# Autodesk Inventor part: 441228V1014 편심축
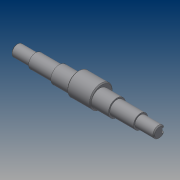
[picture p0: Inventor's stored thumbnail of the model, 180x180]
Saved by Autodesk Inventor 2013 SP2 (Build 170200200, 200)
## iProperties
Created: 2014-12
Part Number: 441228V1014 편심축
Material: Generic
Document SubType Name: Modeling
Designer: CADB105
Density: 1 g/cm^3
Author: CADB105
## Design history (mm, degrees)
sketch "스케치1"
  geometry: L1 (-75.5, 0)-(75.5, 0); L2 (-75.5, 0)-(-75.5, 6); L3 (-75.5, 6)-(-55.5, 6); L4 (-55.5, 6)-(-55.5, 7.5); L5 (-55.5, 7.5)-(-30.5, 7.5); L6 (-30.5, 7.5)-(-30.5, 9); L7 (-30.5, 9)-(30.5, 9); L8 (30.5, 9)-(30.5, 7.5); L9 (30.5, 7.5)-(55.5, 7.5); L10 (55.5, 7.5)-(55.5, 6); L11 (55.5, 6)-(75.5, 6); L12 (75.5, 6)-(75.5, 0); L13 (-12.5, 14)-(12.5, 14); L14 (12.5, 14)-(12.5, 2); L15 (12.5, 2)-(-12.5, 2); L16 (-12.5, 2)-(-12.5, 14); 2 further points
  constraints: 32 end point, 9 parallel, 5 perpendicular, 2 horizontal, 1 coincident, 1 midpoint
  dimensions: "d0" = 151 distance of L1.start L1.end; "d2" = 12 diameter of L3 L1; "d3" = 15 diameter of L5 L1; "d4" = 18 diameter of L7 L1; "d5" = 12 diameter of L11 L1; "d6" = 15 diameter of L9 L1; "d7" = 20 distance of L10.end L11.end; "d8" = 25 distance of L8.end L9.end; "d9" = 20 distance of L2.end L3.end; "d10" = 25 distance of L4.end L5.end; "d12" = 2 distance from line of L15 point (0, 0); "d13" = 24 diameter of L13 L15; "d14" = 18 distance from line of L16 L5.end; "d15" = 18 distance from line of L14 L8.end
revolve "회전1" stored, may be unused: angle "d16" = 90 deg
revolve "회전2" stored, may be unused: angle "d17" = 90 deg
node "작업 평면1"
sketch "스케치2"
  geometry: L1 (75.5, -2.5)-(64, -2.5); L2 (61.5, 0)-(61.5, 0); L3 (64, 2.5)-(75.5, 2.5); L4 (75.5, 2.5)-(75.5, -2.5); L5 (75.5, 6)-(75.5, -6) reference; A1 r 2.5 centre (64, 0) between (61.5, 0) and (64, -2.5); A2 r 2.5 centre (64, 0) between (64, 2.5) and (61.5, 0); 1 further point
  constraints: 8 end point, 4 point on circle, 4 tangent, 2 centre point, 2 parallel, 1 collinear, 1 concentric, 1 horizontal, 1 horizontal alignment, 1 perpendicular
  dimensions: "d19" = 5 distance between parallel lines of L1 L3; "d21" = 2.5 radius of A1; "d22" = 14 distance from line of L2.start L4
extrude "돌출1" cut sketch "스케치2" distance "d23" = 3; taper "d24" = 0 deg
sketch "스케치3"
  geometry: 1 further point
sketch "스케치4"
  geometry: L1 (-75.5, 2.5)-(-64, 2.5); L2 (-61.5, 0)-(-61.5, 0); L3 (-64, -2.5)-(-75.5, -2.5); L4 (-75.5, -2.5)-(-75.5, 2.5); L5 (-75.5, 6)-(-75.5, -6) reference; A1 r 2.5 centre (-64, 0) between (-61.5, 0) and (-64, 2.5); A2 r 2.5 centre (-64, 0) between (-64, -2.5) and (-61.5, 0); 1 further point
  constraints: 8 end point, 4 point on circle, 4 tangent, 2 centre point, 2 parallel, 1 collinear, 1 concentric, 1 horizontal, 1 horizontal alignment, 1 perpendicular
  dimensions: "d25" = 5 distance between parallel lines of L1 L3; "d27" = 2.5 radius of A1; "d28" = 14 distance from line of L2.start L4
extrude "돌출2" cut sketch "스케치4" distance "d29" = 3; taper "d30" = 0 deg
chamfer "모따기1" distance "d31" = 1; stored, may be unused: second distance "d32" = 2, angle "d33" = 45 deg
chamfer "모따기2" distance "d34" = 1; stored, may be unused: second distance "d35" = 2, angle "d36" = 45 deg
node "솔리드1"
other parameters: "d18" = 6
